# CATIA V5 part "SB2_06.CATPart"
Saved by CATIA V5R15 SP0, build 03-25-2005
Part number: SB2_06
Material "Crisp Brown": density 7860 kg/m3, Young's modulus 2e+11 Pa, Poisson ratio 0.266
Bounding box of the stored display mesh (mm): x 0 to 158, y 0 to 474, z 0 to 49.2
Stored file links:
  E:\#01 CATIA Lecture Materials\#06 DMU\#11 DMU Page01 KIN EX11\SB2_06.CATPart
  C:\Program Files\Dassault Systemes\B20\win_b64\startup\materials\Catalog.CATMaterial
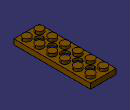
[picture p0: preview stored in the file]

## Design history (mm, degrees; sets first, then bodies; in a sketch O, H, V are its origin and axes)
Body1 (main body), material "Crisp Brown"
  Sketch1 on xy-plane, origin (0, 0, 0), H (1, 0, 0), V (0, 1, 0)
    circle A1 centre (39.5, 39.5) radius 24.5
    point P1 (39.5, 39.5)
    radius A1 = 24.5
    distance P1 H = 39.5
    distance P1 V = 39.5
  Pad1: profile Sketch1, direction (0, 0, 1), length 49.2
  Sketch2 on xy-plane, origin (0, 0, 0), H (1, 0, 0), V (0, 1, 0)
    point P1 (0, 474)
    line L1 (0, 474) -> (158, 474)
    line L2 (158, 474) -> (158, 0)
    line L3 (158, 0) -> (0, 0)
    line L4 (0, 0) -> (0, 474)
    point P3 (158, 0)
    distance L2 L4 = 158
    distance L1 L3 = 474 {= RectPattern2.Nb1  * 79mm}
    coincidence: P1 V, P3 H
    horizontal: L1 H, L3 H
    vertical: L2 V, L4 V
  Pad2: profile Sketch2, direction (0, 0, 1), length 32
  RectPattern1: of Pad1, direction 1 instances 2, spacing 79, along edge [face of Pad2 from Sketch2.L3 | end face of Pad2]
  RectPattern2: of RectPattern1, direction 1 instances 6, spacing 79, along edge [face of Pad2 from Sketch2.L2 | end face of Pad2]
  Shell1: ExtOffset 0, Face face of Pad2, IntOffset 15
  Sketch3 on end face of Pad2, origin (0, 0, 32), H (1, 0, 0), V (0, 1, 0)
    circle A1 centre (79, 79) radius 24.5
    point P1 (79, 79)
    reference projected point E1 (118.5, 118.5) from axis of face of RectPattern2
    reference projected point E2 (39.5, 118.5) from axis of face of RectPattern2
    reference projected point E3 (118.5, 39.5) from axis of face of RectPattern1
    reference projected point E4 (118.5, 118.5) from axis of face of RectPattern2
    radius A1 = 24.5
    equidistance: E1 E2 P1, E3 E4 P1
  Pocket1: profile Sketch3, direction (0, 0, -1), length 20
  RectPattern3: of Pocket1, direction 1 instances 5 {= RectPattern2.Nb1 - 1}, spacing 79, along edge [face of Pad2 from Sketch2.L4 | end face of Pad2] reversed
